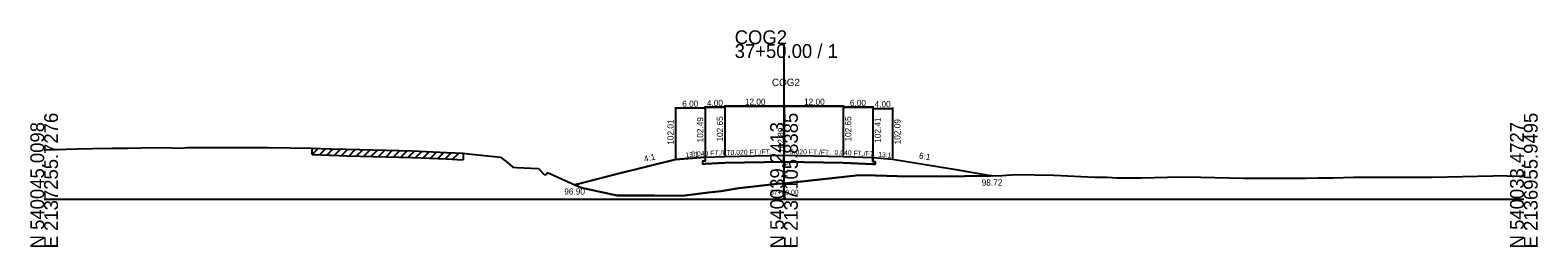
# Model space of a CAD drawing. Extents: x -13397 to 2303, y -10 to 39059.
# Drawn here: x 997.2 to 1302.8, y 14990.3 to 15034.2 of the extents above; entities that cross this region are included whole.
import ezdxf

# ---------------------------------------------------------------- set-up
doc = ezdxf.new("R2010")
doc.units = 0
for name, color, linetype in [('Level 5', 7, 'Continuous'), ('Level 53', 7, 'Continuous'), ('Level 54', 7, 'Continuous'), ('Level 55', 7, 'Continuous'), ('Level 7', 7, 'Continuous'), ('RD_GPK_XS_Cell', 7, 'Continuous'), ('RD_XS_EwShp', 7, 'Continuous'), ('RD_XS_ExGround', 7, 'Continuous'), ('RD_XS_ExPaveRet', 7, 'Continuous'), ('RD_XS_Pave', 7, 'Continuous'), ('RD_XS_TX_Baseline', 7, 'Continuous'), ('RD_XS_TX_Elev_EX', 7, 'Continuous'), ('RD_XS_TX_Elev_PR', 7, 'Continuous'), ('RD_XS_TX_Station', 7, 'Continuous')]:
    doc.layers.add(name, color=color, linetype=linetype)

msp = doc.modelspace()

# ---------------------------------------------------------------- linework, layer by layer
at = {"layer": 'Level 5'}
for p, q in [((1134, 15007.66), (1133.5, 15007.64)), ((1133.5, 15007.64), (1133.5, 15007.14)), ((1133.5, 15007.14), (1134, 15007.16)), ((1134, 15008.49), (1134, 15007.66)), ((1138, 15007.32), (1134, 15007.16)), ((1138, 15007.32), (1134, 15007.16)), ((1138, 15007.32), (1134, 15007.16)), ((1134, 15007.16), (1138, 15007.32)), ((1150, 15007.56), (1138, 15007.32)), ((1150, 15007.56), (1138, 15007.32)), ((1150, 15007.56), (1138, 15007.32)), ((1138, 15007.32), (1150, 15007.56)), ((1138, 15007.32), (1150, 15007.56)), ((1162, 15007.32), (1150, 15007.56)), ((1162, 15007.32), (1150, 15007.56)), ((1150, 15007.56), (1162, 15007.32)), ((1150, 15007.56), (1162, 15007.32)), ((1150, 15007.56), (1162, 15007.32)), ((1168, 15007.08), (1162, 15007.32)), ((1162, 15007.32), (1168, 15007.08)), ((1162, 15007.32), (1168, 15007.08)), ((1162, 15007.32), (1168, 15007.08)), ((1168, 15008.41), (1168, 15007.58)), ((1168, 15007.58), (1168.5, 15007.56)), ((1168.5, 15007.06), (1168, 15007.08)), ((1168.5, 15007.56), (1168.5, 15007.06))]:
    msp.add_line(p, q, dxfattribs=at)
at = {"layer": 'Level 54'}
for p, q in [((1128, 15018.64), (1128, 15008.21)), ((1134, 15018.44), (1128, 15018.44)), ((1134, 15018.8), (1134, 15008.69)), ((1134, 15018.8), (1134, 15008.69)), ((1134, 15018.8), (1134, 15008.69)), ((1134, 15018.8), (1134, 15008.69)), ((1134, 15018.64), (1134, 15008.69)), ((1134, 15018.6), (1138, 15018.6)), ((1134, 15018.6), (1138, 15018.6)), ((1134, 15018.6), (1138, 15018.6)), ((1138, 15018.6), (1134, 15018.6)), ((1138, 15019.04), (1138, 15008.85)), ((1138, 15019.04), (1138, 15008.85)), ((1138, 15019.04), (1138, 15008.85)), ((1138, 15019.04), (1138, 15008.85)), ((1138, 15019.04), (1138, 15008.85)), ((1138, 15018.84), (1150, 15018.84)), ((1138, 15018.84), (1150, 15018.84)), ((1138, 15018.84), (1150, 15018.84)), ((1150, 15018.84), (1138, 15018.84)), ((1150, 15018.84), (1138, 15018.84)), ((1138, 15018.8), (1138, 15008.85)), ((1138, 15018.8), (1138, 15008.85)), ((1138, 15018.8), (1138, 15008.85)), ((1138, 15018.8), (1138, 15008.85)), ((1150, 15019.04), (1150, 15009.09)), ((1150, 15019.04), (1150, 15009.09)), ((1150, 15019.04), (1150, 15009.09)), ((1150, 15019.04), (1150, 15009.09)), ((1150, 15019.04), (1150, 15009.09)), ((1150, 15019.04), (1150, 15009.09)), ((1150, 15019.04), (1150, 15009.09)), ((1150, 15019.04), (1150, 15009.09)), ((1150, 15019.04), (1150, 15009.09)), ((1150, 15019.04), (1150, 15009.09)), ((1150, 15018.84), (1162, 15018.84)), ((1150, 15018.84), (1162, 15018.84)), ((1162, 15018.84), (1150, 15018.84)), ((1162, 15018.84), (1150, 15018.84)), ((1162, 15018.84), (1150, 15018.84)), ((1162, 15019.04), (1162, 15008.85)), ((1162, 15019.04), (1162, 15008.85)), ((1162, 15019.04), (1162, 15008.85)), ((1162, 15019.04), (1162, 15008.85)), ((1162, 15019.04), (1162, 15008.85)), ((1162, 15018.8), (1162, 15008.85)), ((1162, 15018.8), (1162, 15008.85)), ((1162, 15018.8), (1162, 15008.85)), ((1162, 15018.8), (1162, 15008.85)), ((1162, 15018.6), (1168, 15018.6)), ((1168, 15018.6), (1162, 15018.6)), ((1168, 15018.6), (1162, 15018.6)), ((1168, 15018.6), (1162, 15018.6)), ((1168, 15018.8), (1168, 15008.61)), ((1168, 15018.8), (1168, 15008.61)), ((1168, 15018.8), (1168, 15008.61)), ((1168, 15018.8), (1168, 15008.61)), ((1168, 15018.56), (1168, 15008.61)), ((1168, 15018.36), (1172, 15018.36)), ((1172, 15018.56), (1172, 15008.29))]:
    msp.add_line(p, q, dxfattribs=at)
at = {"layer": 'Level 7'}
for p, q in [((1128, 15008.01), (1116, 15005.01)), ((1134, 15008.49), (1128, 15008.01)), ((1168, 15008.41), (1172, 15008.09)), ((1172, 15008.09), (1184, 15006.09)), ((1184, 15006.09), (1192.23, 15004.72)), ((1116, 15005.01), (1107.57, 15002.9))]:
    msp.add_line(p, q, dxfattribs=at)
at = {"layer": 'RD_GPK_XS_Cell'}
for p, q in [((1150, 15000), (1150, 15031.39)), ((1000, 15000), (1150, 15000)), ((1150, 15000), (1300, 15000))]:
    msp.add_line(p, q, dxfattribs=at)
at = {"layer": 'RD_XS_EwShp'}
msp.add_lwpolyline([(1134, 15008.49), (1134, 15007.66), (1133.5, 15007.64), (1133.5, 15007.14), (1134, 15007.16), (1138, 15007.32), (1150, 15007.56), (1162, 15007.32), (1168, 15007.08), (1168.5, 15007.06), (1168.5, 15007.56), (1168, 15007.58), (1168, 15008.41), (1172, 15008.09), (1184, 15006.09), (1192.23, 15004.72), (1191.95, 15004.71), (1181.29, 15004.59), (1172.93, 15004.63), (1166.39, 15004.84), (1164.6, 15004.74), (1153.6, 15003.53), (1150, 15003.18), (1148.69, 15003.05), (1140.82, 15002.17), (1137.27, 15001.61), (1134.71, 15001.35), (1129.34, 15000.64), (1123.75, 15000.69), (1116.17, 15000.74), (1110.25, 15001.97), (1108.95, 15002.29), (1108.32, 15002.57), (1107.57, 15002.9), (1116, 15005.01), (1128, 15008.01)], close=True, dxfattribs=at)
at = {"layer": 'RD_XS_ExGround'}
for p, q in [((1000, 15009.96), (1006.7, 15010.19)), ((1006.7, 15010.19), (1009.78, 15010.23)), ((1009.78, 15010.23), (1013.69, 15010.3)), ((1013.69, 15010.3), (1016.94, 15010.34)), ((1016.94, 15010.34), (1019.64, 15010.38)), ((1019.64, 15010.38), (1024.06, 15010.43)), ((1024.06, 15010.43), (1025.88, 15010.35)), ((1025.88, 15010.35), (1027.72, 15010.32)), ((1027.72, 15010.32), (1028.97, 15010.46)), ((1028.97, 15010.46), (1031.19, 15010.45)), ((1031.19, 15010.45), (1032.59, 15010.46)), ((1032.59, 15010.46), (1045.42, 15010.46)), ((1045.42, 15010.46), (1054.31, 15010.3)), ((1054.31, 15010.3), (1057.75, 15010.17)), ((1057.75, 15010.17), (1058.23, 15010.16)), ((1058.23, 15010.16), (1061.27, 15010.08)), ((1061.27, 15010.08), (1074.66, 15009.75)), ((1074.66, 15009.75), (1081.56, 15009.42)), ((1081.56, 15009.42), (1084.96, 15009.27)), ((1084.96, 15009.27), (1085.98, 15009.15)), ((1085.98, 15009.15), (1092.49, 15008.48)), ((1092.49, 15008.48), (1094, 15007.36)), ((1094, 15007.36), (1095.05, 15006.47)), ((1095.05, 15006.47), (1095.77, 15006.42)), ((1095.77, 15006.42), (1100.25, 15006.16)), ((1100.25, 15006.16), (1101.45, 15004.89)), ((1101.45, 15004.89), (1101.91, 15005.04)), ((1101.91, 15005.04), (1102.05, 15005.35)), ((1102.05, 15005.35), (1108.32, 15002.57)), ((1140.82, 15002.17), (1148.69, 15003.05)), ((1148.69, 15003.05), (1150, 15003.18)), ((1150, 15003.18), (1153.6, 15003.53)), ((1153.6, 15003.53), (1164.6, 15004.74)), ((1164.6, 15004.74), (1166.39, 15004.84)), ((1166.39, 15004.84), (1172.93, 15004.63)), ((1172.93, 15004.63), (1181.29, 15004.59)), ((1181.29, 15004.59), (1191.95, 15004.71)), ((1191.95, 15004.71), (1194.21, 15004.76)), ((1194.21, 15004.76), (1196.96, 15004.95)), ((1196.96, 15004.95), (1204.74, 15004.84)), ((1204.74, 15004.84), (1213.03, 15004.41)), ((1213.03, 15004.41), (1215.53, 15004.43)), ((1215.53, 15004.43), (1217.52, 15004.31)), ((1217.52, 15004.31), (1222.57, 15004.29)), ((1222.57, 15004.29), (1230.3, 15004.5)), ((1230.3, 15004.5), (1234.53, 15004.46)), ((1234.53, 15004.46), (1243.09, 15004.26)), ((1243.09, 15004.26), (1244.01, 15004.24)), ((1244.01, 15004.24), (1245.05, 15004.25)), ((1245.05, 15004.25), (1255.87, 15004.23)), ((1255.87, 15004.23), (1258.29, 15004.3)), ((1258.29, 15004.3), (1261.35, 15004.28)), ((1261.35, 15004.28), (1265.45, 15004.4)), ((1265.45, 15004.4), (1277.77, 15004.42)), ((1277.77, 15004.42), (1279.83, 15004.45)), ((1279.83, 15004.45), (1281.44, 15004.42)), ((1281.44, 15004.42), (1293.7, 15004.72)), ((1293.7, 15004.72), (1294.22, 15004.75)), ((1294.22, 15004.75), (1299.02, 15004.62)), ((1299.02, 15004.62), (1300, 15004.6)), ((1108.32, 15002.57), (1108.95, 15002.29)), ((1108.95, 15002.29), (1110.25, 15001.97)), ((1110.25, 15001.97), (1116.17, 15000.74)), ((1116.17, 15000.74), (1123.75, 15000.69)), ((1123.75, 15000.69), (1129.34, 15000.64)), ((1129.34, 15000.64), (1134.71, 15001.35)), ((1134.71, 15001.35), (1137.27, 15001.61)), ((1137.27, 15001.61), (1140.82, 15002.17))]:
    msp.add_line(p, q, dxfattribs=at)
at = {"layer": 'RD_XS_ExPaveRet'}
for p, q in [((1054.31, 15009), (1054.31, 15010.3)), ((1054.31, 15009), (1055.56, 15010.25)), ((1054.31, 15009), (1057.75, 15008.87)), ((1055.81, 15008.94), (1057.06, 15010.19)), ((1057.31, 15008.88), (1058.57, 15010.15)), ((1058.81, 15008.84), (1060.08, 15010.11)), ((1060.31, 15008.81), (1061.58, 15010.08)), ((1061.81, 15008.77), (1063.08, 15010.04)), ((1063.31, 15008.73), (1064.58, 15010)), ((1064.81, 15008.69), (1066.08, 15009.96)), ((1066.31, 15008.66), (1067.58, 15009.93)), ((1067.81, 15008.62), (1069.08, 15009.89)), ((1069.31, 15008.58), (1070.58, 15009.85)), ((1070.81, 15008.54), (1072.08, 15009.81)), ((1072.31, 15008.51), (1073.58, 15009.77)), ((1073.81, 15008.47), (1075.07, 15009.73)), ((1075.31, 15008.42), (1076.55, 15009.66)), ((1076.81, 15008.35), (1078.05, 15009.59)), ((1078.31, 15008.27), (1079.55, 15009.52)), ((1079.81, 15008.2), (1081.05, 15009.44)), ((1081.31, 15008.13), (1082.55, 15009.38)), ((1082.81, 15008.06), (1084.05, 15009.31)), ((1084.96, 15009.27), (1084.96, 15007.97)), ((1057.75, 15008.87), (1058.23, 15008.86)), ((1058.23, 15008.86), (1061.27, 15008.78)), ((1061.27, 15008.78), (1074.66, 15008.45)), ((1074.66, 15008.45), (1081.56, 15008.12)), ((1081.56, 15008.12), (1084.96, 15007.97))]:
    msp.add_line(p, q, dxfattribs=at)
at = {"layer": 'RD_XS_Pave'}
for p, q in [((1134, 15008.49), (1138, 15008.65)), ((1138, 15008.65), (1150, 15008.89)), ((1150, 15008.89), (1162, 15008.65)), ((1162, 15008.65), (1168, 15008.41))]:
    msp.add_line(p, q, dxfattribs=at)

# ---------------------------------------------------------------- texts
at = {"layer": 'Level 53'}
for s, rotation, p in [('102.01', 90, (1127.62, 15011.01)), ('102.49', 90, (1133.62, 15011.49)), ('102.65', 90, (1137.63, 15011.65)), ('102.65', 90, (1137.63, 15011.65)), ('102.65', 90, (1137.63, 15011.65)), ('102.65', 90, (1163.63, 15011.65)), ('102.65', 90, (1163.63, 15011.65)), ('102.65', 90, (1163.63, 15011.65)), ('102.41', 90, (1169.62, 15011.41)), ('102.09', 90, (1173.62, 15011.09)), ('4:1', 14.0362, (1121.76, 15007.48)), ('6:1', 350.5377, (1177.3, 15008.22))]:
    msp.add_text(s, height=1.25, rotation=rotation, dxfattribs=at).set_placement(p)
for s, p in [('98.72', (1190.09, 15002.72)), ('96.90', (1105.46, 15000.9))]:
    msp.add_text(s, height=1.25, dxfattribs=at).set_placement(p)
at = {"layer": 'Level 54'}
for s, p in [('6.00', (1129.37, 15018.69)), ('4.00', (1134.37, 15018.85)), ('4.00', (1134.37, 15018.85)), ('4.00', (1134.37, 15018.85)), ('4.00', (1134.37, 15018.85)), ('12.00', (1142.07, 15019.09)), ('12.00', (1142.07, 15019.09)), ('12.00', (1142.07, 15019.09)), ('12.00', (1142.07, 15019.09)), ('12.00', (1142.07, 15019.09)), ('12.00', (1154.07, 15019.09)), ('12.00', (1154.07, 15019.09)), ('12.00', (1154.07, 15019.09)), ('12.00', (1154.07, 15019.09)), ('12.00', (1154.07, 15019.09)), ('6.00', (1163.37, 15018.85)), ('6.00', (1163.37, 15018.85)), ('6.00', (1163.37, 15018.85)), ('6.00', (1163.37, 15018.85)), ('4.00', (1168.37, 15018.61))]:
    msp.add_text(s, height=1.25, dxfattribs=at).set_placement(p)
at = {"layer": 'Level 55'}
for s, rotation, p in [('13:1', 4.5739, (1130.03, 15008.42)), ('0.040 FT./FT.', 2.2906, (1131.22, 15008.63)), ('0.040 FT./FT.', 2.2906, (1131.22, 15008.63)), ('0.040 FT./FT.', 2.2906, (1131.22, 15008.63)), ('0.040 FT./FT.', 2.2906, (1131.22, 15008.63)), ('0.020 FT./FT.', 1.1458, (1139.17, 15008.92)), ('0.020 FT./FT.', 1.1458, (1139.17, 15008.92)), ('0.020 FT./FT.', 1.1458, (1139.17, 15008.92)), ('0.020 FT./FT.', 1.1458, (1139.17, 15008.92)), ('0.020 FT./FT.', 1.1458, (1139.17, 15008.92)), ('0.020 FT./FT.', 358.8542, (1151.18, 15009.12)), ('0.020 FT./FT.', 358.8542, (1151.18, 15009.12)), ('0.020 FT./FT.', 358.8542, (1151.18, 15009.12)), ('0.020 FT./FT.', 358.8542, (1151.18, 15009.12)), ('0.020 FT./FT.', 358.8542, (1151.18, 15009.12)), ('0.040 FT./FT.', 357.7094, (1160.24, 15008.97)), ('0.040 FT./FT.', 357.7094, (1160.24, 15008.97)), ('0.040 FT./FT.', 357.7094, (1160.24, 15008.97)), ('0.040 FT./FT.', 357.7094, (1160.24, 15008.97)), ('13:1', 355.4261, (1169.07, 15008.58))]:
    msp.add_text(s, height=1, rotation=rotation, dxfattribs=at).set_placement(p)
at = {"layer": 'RD_GPK_XS_Cell'}
for s, p in [('COG2', (1140, 15031.39)), ('37+50.00 / 1', (1140, 15028.59))]:
    msp.add_text(s, height=2.8, dxfattribs=at).set_placement(p)
for s, p in [('N 540045.0098', (1000, 14990)), ('E 2137255.7276', (1002.8, 14990)), ('N 540039.2413', (1150, 14990)), ('E 2137105.8385', (1152.8, 14990)), ('N 540033.4727', (1300, 14990)), ('E 2136955.9495', (1302.8, 14990))]:
    msp.add_text(s, height=2.8, rotation=90, dxfattribs=at).set_placement(p)
at = {"layer": 'RD_XS_TX_Baseline'}
msp.add_text('COG2', height=1.5, dxfattribs=at).set_placement((1147.55, 15022.89))
at = {"layer": 'RD_XS_TX_Elev_EX'}
msp.add_text('97.18', height=1, rotation=90, dxfattribs=at).set_placement((1150.75, 15004.18))
at = {"layer": 'RD_XS_TX_Elev_PR'}
msp.add_text(' 102.89', height=1.25, rotation=90, dxfattribs=at).set_placement((1150, 15008.89))
at = {"layer": 'RD_XS_TX_Station'}
msp.add_text('37+50.00', height=1, dxfattribs=at).set_placement((1147.18, 15000.89))

doc.saveas('drawing.dxf')
